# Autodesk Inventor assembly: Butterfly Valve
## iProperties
Shininess: 64.0
Length Units: 11269
Angle Units: 11279
Time Units: 11290
Mass Units: 11283
Length Display Precision: 3
Angle Display Precision: 2
Created: 2002-01
Part Number: Butterfly Valve
Document SubType Name: Assembly
Designer: ***
Density: 0.0
Volumn: 0.0
Area: 0.0
PropertySet Name: Model Information
Control State: 0
Master: False
Checked Out: False
Author: ***
